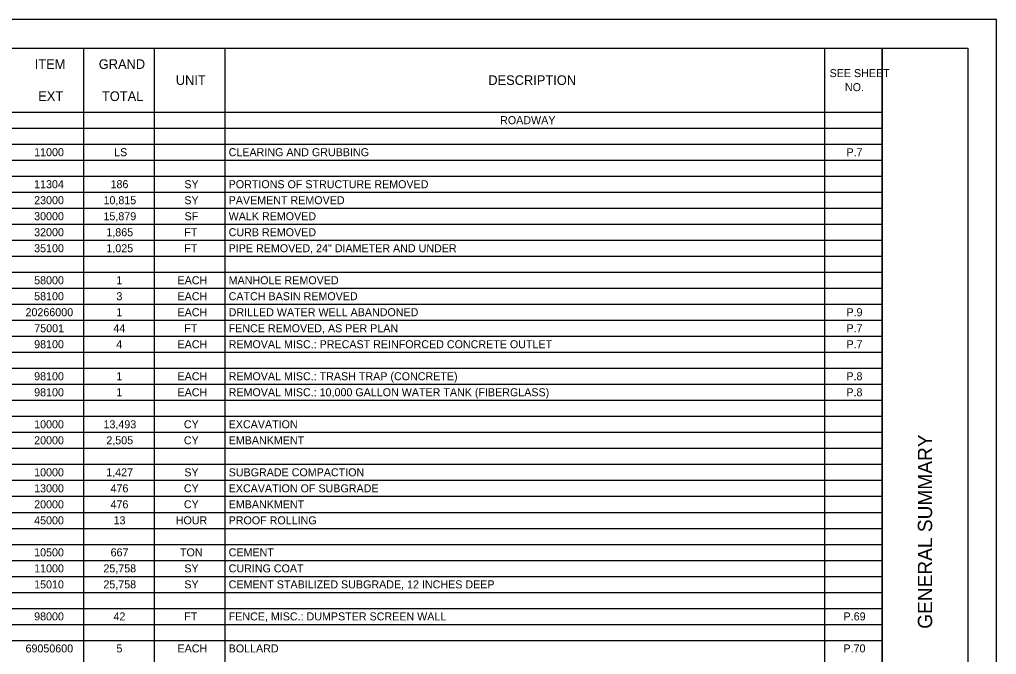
# Model space of a CAD drawing. Extents: x 0 to 34, y 0 to 22.
# Drawn here: x 16.91 to 34, y 10.9 to 22 of the extents above; entities that cross this region are included whole.
import ezdxf

# ---------------------------------------------------------------- set-up
doc = ezdxf.new("R2010")
doc.units = 0
for name, color, linetype in [('SH_Border', 7, 'Continuous'), ('SH_Cut_Line', 7, 'Continuous'), ('SH_Data', 7, 'Continuous'), ('SH_Text', 7, 'Continuous')]:
    doc.layers.add(name, color=color, linetype=linetype)

msp = doc.modelspace()

# ---------------------------------------------------------------- linework, layer by layer
at = {"layer": 'SH_Border'}
msp.add_line((32, 0.5), (32, 21.5), dxfattribs=at)
msp.add_lwpolyline([(1.5, 21.5), (33.5, 21.5), (33.5, 0.5), (1.5, 0.5)], close=True, dxfattribs=at)
at = {"layer": 'SH_Cut_Line'}
msp.add_lwpolyline([(0, 0), (34, 0), (34, 22), (0, 22)], close=True, dxfattribs=at)
at = {"layer": 'SH_Text'}
for p, q in [((1.5, 21.5), (32, 21.5)), ((18.035, 21.5), (18.035, 0.502)), ((19.27, 21.5), (19.27, 0.502)), ((20.505, 21.5), (20.505, 0.502)), ((30.995, 21.5), (30.995, 0.502)), ((32, 21.5), (32, 0.502)), ((1.5, 20.38), (32, 20.38)), ((1.5, 20.1), (32, 20.1)), ((1.5, 19.82), (32, 19.82)), ((1.5, 19.54), (32, 19.54)), ((1.5, 19.26), (32, 19.26)), ((1.5, 18.98), (32, 18.98)), ((1.5, 18.7), (32, 18.7)), ((1.5, 18.42), (32, 18.42)), ((1.5, 18.14), (32, 18.14)), ((1.5, 17.86), (32, 17.86)), ((1.5, 17.58), (32, 17.58)), ((1.5, 17.3), (32, 17.3)), ((1.5, 17.021), (32, 17.021)), ((1.5, 16.741), (32, 16.741)), ((1.5, 16.461), (32, 16.461)), ((1.5, 16.181), (32, 16.181)), ((1.5, 15.901), (32, 15.901)), ((1.5, 15.621), (32, 15.621)), ((1.5, 15.341), (32, 15.341)), ((1.5, 15.061), (32, 15.061)), ((1.5, 14.781), (32, 14.781)), ((1.5, 14.501), (32, 14.501)), ((1.5, 14.221), (32, 14.221)), ((1.5, 13.941), (32, 13.941)), ((1.5, 13.661), (32, 13.661)), ((1.5, 13.381), (32, 13.381)), ((1.5, 13.101), (32, 13.101)), ((1.5, 12.821), (32, 12.821)), ((1.5, 12.541), (32, 12.541)), ((1.5, 12.261), (32, 12.261)), ((1.5, 11.981), (32, 11.981)), ((1.5, 11.701), (32, 11.701)), ((1.5, 11.421), (32, 11.421)), ((1.5, 11.141), (32, 11.141))]:
    msp.add_line(p, q, dxfattribs=at)

# ---------------------------------------------------------------- texts
at = {"layer": 'SH_Data'}
msp.add_text('GENERAL SUMMARY', height=0.25, rotation=90, dxfattribs=at).set_placement((32.875, 11.344))
at = {"layer": 'SH_Text'}
for s, height, p in [('ITEM', 0.168, (17.179, 21.136)), ('GRAND', 0.168, (18.299, 21.136)), ('UNIT', 0.168, (19.647, 20.856)), ('DESCRIPTION', 0.16798, (25.112, 20.856)), ('SEE SHEET ', 0.14, (31.081, 20.993)), ('NO.', 0.14, (31.35, 20.748)), ('EXT', 0.168, (17.24, 20.576)), ('TOTAL', 0.168, (18.355, 20.576)), ('ROADWAY', 0.14, (25.319, 20.17)), ('11000', 0.14, (17.169, 19.61)), ('LS', 0.14, (18.568, 19.61)), ('CLEARING AND GRUBBING', 0.13998, (20.571, 19.61)), ('P.7', 0.14, (31.376, 19.61)), ('11304', 0.14, (17.168, 19.05)), ('186', 0.14, (18.505, 19.05)), ('SY', 0.14, (19.796, 19.05)), ('PORTIONS OF STRUCTURE REMOVED', 0.13998, (20.571, 19.05)), ('23000', 0.14, (17.169, 18.77)), ('10,815', 0.14, (18.382, 18.77)), ('SY', 0.14, (19.796, 18.77)), ('PAVEMENT REMOVED', 0.13998, (20.571, 18.77)), ('30000', 0.14, (17.169, 18.49)), ('15,879', 0.14, (18.381, 18.49)), ('SF', 0.14, (19.8, 18.49)), ('WALK REMOVED', 0.13998, (20.571, 18.49)), ('32000', 0.14, (17.169, 18.21)), ('1,865', 0.14, (18.432, 18.21)), ('FT', 0.14, (19.794, 18.21)), ('CURB REMOVED', 0.13998, (20.571, 18.21)), ('35100', 0.14, (17.169, 17.93)), ('1,025', 0.14, (18.432, 17.93)), ('FT', 0.14, (19.794, 17.93)), ('PIPE REMOVED, 24" DIAMETER AND UNDER', 0.13998, (20.571, 17.93)), ('58000', 0.14, (17.169, 17.37)), ('1', 0.14, (18.607, 17.37)), ('EACH', 0.14, (19.677, 17.37)), ('MANHOLE REMOVED', 0.13998, (20.571, 17.37)), ('58100', 0.14, (17.169, 17.091)), ('3', 0.14, (18.608, 17.091)), ('EACH', 0.14, (19.677, 17.091)), ('CATCH BASIN REMOVED', 0.13998, (20.571, 17.091)), ('20266000', 0.14, (17.018, 16.811)), ('1', 0.14, (18.607, 16.811)), ('EACH', 0.14, (19.677, 16.811)), ('DRILLED WATER WELL ABANDONED', 0.13998, (20.571, 16.811)), ('P.9', 0.14, (31.376, 16.811)), ('75001', 0.14, (17.171, 16.531)), ('44', 0.14, (18.554, 16.531)), ('FT', 0.14, (19.794, 16.531)), ('FENCE REMOVED, AS PER PLAN', 0.13998, (20.571, 16.531)), ('P.7', 0.14, (31.376, 16.531)), ('98100', 0.14, (17.169, 16.251)), ('4', 0.14, (18.605, 16.251)), ('EACH', 0.14, (19.677, 16.251)), ('REMOVAL MISC.: PRECAST REINFORCED CONCRETE OUTLET', 0.13998, (20.571, 16.251)), ('P.7', 0.14, (31.376, 16.251)), ('98100', 0.14, (17.169, 15.691)), ('1', 0.14, (18.607, 15.691)), ('EACH', 0.14, (19.677, 15.691)), ('REMOVAL MISC.: TRASH TRAP (CONCRETE)', 0.13998, (20.571, 15.691)), ('P.8', 0.14, (31.375, 15.691)), ('98100', 0.14, (17.169, 15.411)), ('1', 0.14, (18.607, 15.411)), ('EACH', 0.14, (19.677, 15.411)), ('REMOVAL MISC.: 10,000 GALLON WATER TANK (FIBERGLASS)', 0.13998, (20.571, 15.411)), ('P.8', 0.14, (31.375, 15.411)), ('10000', 0.14, (17.169, 14.851)), ('13,493', 0.14, (18.382, 14.851)), ('CY', 0.14, (19.788, 14.851)), ('EXCAVATION', 0.14, (20.571, 14.851)), ('20000', 0.14, (17.169, 14.571)), ('2,505', 0.14, (18.432, 14.571)), ('CY', 0.14, (19.788, 14.571)), ('EMBANKMENT', 0.14, (20.571, 14.571)), ('10000', 0.14, (17.169, 14.011)), ('1,427', 0.14, (18.431, 14.011)), ('SY', 0.14, (19.796, 14.011)), ('SUBGRADE COMPACTION', 0.13998, (20.571, 14.011)), ('13000', 0.14, (17.169, 13.731)), ('476', 0.14, (18.505, 13.731)), ('CY', 0.14, (19.788, 13.731)), ('EXCAVATION OF SUBGRADE', 0.13998, (20.571, 13.731)), ('20000', 0.14, (17.169, 13.451)), ('476', 0.14, (18.505, 13.451)), ('CY', 0.14, (19.788, 13.451)), ('EMBANKMENT', 0.14, (20.571, 13.451)), ('45000', 0.14, (17.169, 13.171)), ('13', 0.14, (18.558, 13.171)), ('HOUR', 0.14, (19.646, 13.171)), ('PROOF ROLLING', 0.13998, (20.571, 13.171)), ('10500', 0.14, (17.169, 12.611)), ('667', 0.14, (18.506, 12.611)), ('TON', 0.14, (19.72, 12.611)), ('CEMENT', 0.14, (20.571, 12.611)), ('11000', 0.14, (17.169, 12.331)), ('25,758', 0.14, (18.38, 12.331)), ('SY', 0.14, (19.796, 12.331)), ('CURING COAT', 0.13998, (20.571, 12.331)), ('15010', 0.14, (17.169, 12.051)), ('25,758', 0.14, (18.38, 12.051)), ('SY', 0.14, (19.796, 12.051)), ('CEMENT STABILIZED SUBGRADE, 12 INCHES DEEP', 0.13998, (20.571, 12.051)), ('98000', 0.14, (17.169, 11.491)), ('42', 0.14, (18.557, 11.491)), ('FT', 0.14, (19.794, 11.491)), ('FENCE, MISC.: DUMPSTER SCREEN WALL', 0.13998, (20.571, 11.491)), ('P.69', 0.14, (31.326, 11.491)), ('69050600', 0.14, (17.018, 10.931)), ('5', 0.14, (18.608, 10.931)), ('EACH', 0.14, (19.677, 10.931)), ('BOLLARD', 0.14, (20.571, 10.931)), ('P.70', 0.14, (31.324, 10.931))]:
    msp.add_text(s, height=height, dxfattribs=at).set_placement(p)

doc.saveas('drawing.dxf')
